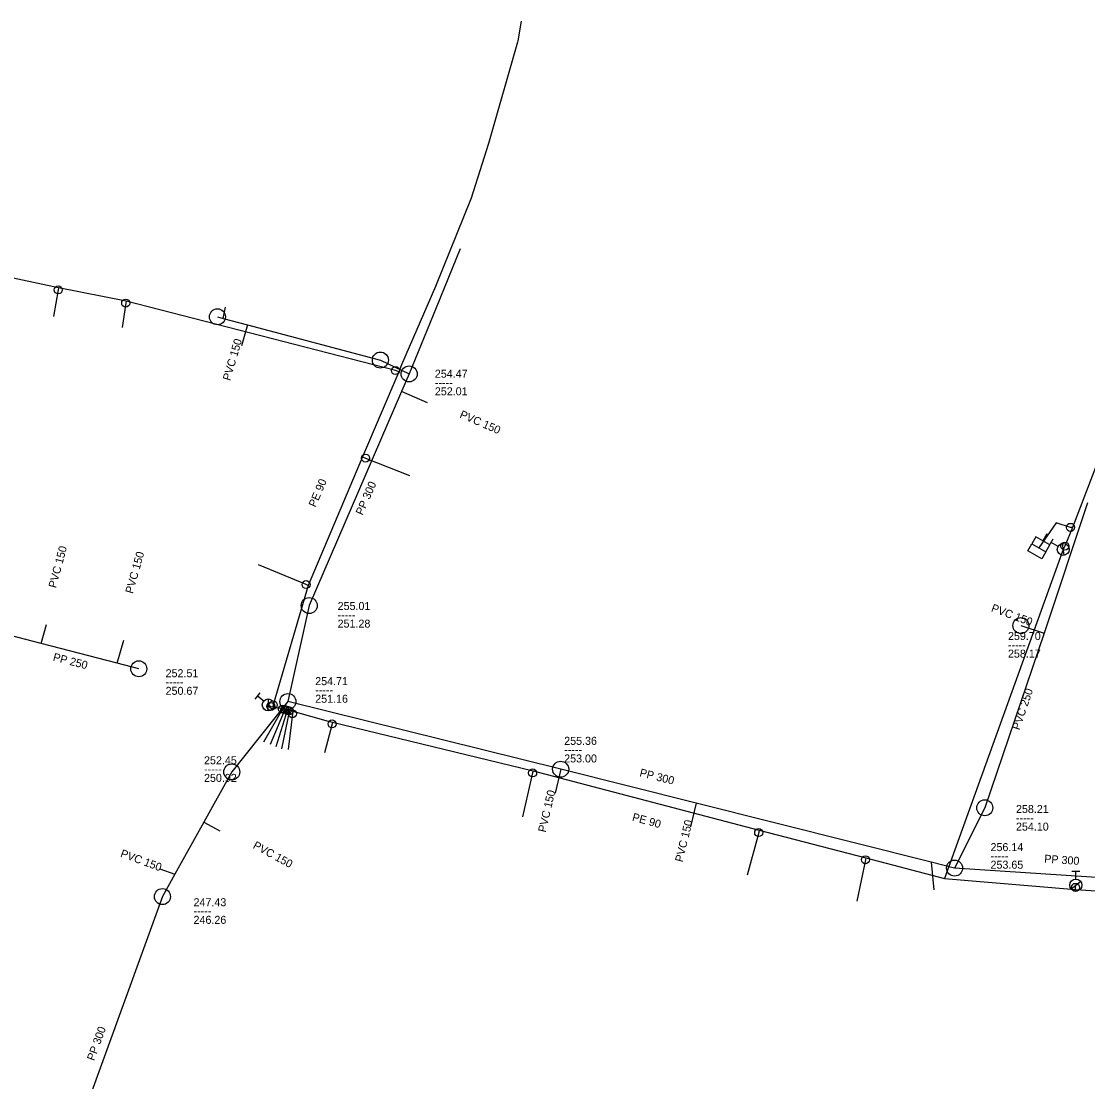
# Model space of a CAD drawing. Extents: x -771681 to -770485, y -1050143 to -1049574.
# Drawn here: x -771433.4 to -771300.2, y -1049821.1 to -1049688.6 of the extents above; entities that cross this region are included whole.
import ezdxf

# ---------------------------------------------------------------- set-up
doc = ezdxf.new("R2010")
doc.units = 0
doc.layers.add('Level 0', color=7, linetype='Continuous')

msp = doc.modelspace()

# ---------------------------------------------------------------- linework, layer by layer
at = {"layer": 'Level 0'}
for p, q in [((-771370.98, -1049688.58), (-771371.4, -1049691.01)), ((-771371.42, -1049691.2), (-771375.04, -1049703.86)), ((-771371.4, -1049691.01), (-771371.42, -1049691.2)), ((-771375.04, -1049703.86), (-771377.2, -1049710.67)), ((-771377.2, -1049710.67), (-771381.66, -1049721.72)), ((-771428.76, -1049721.9), (-771458.82, -1049715.48)), ((-771378.58, -1049717.02), (-771381.58, -1049724.37)), ((-771288.8, -1049717.07), (-771302.09, -1049751.83)), ((-771428.76, -1049721.9), (-771428.8, -1049722.15)), ((-771420.34, -1049723.55), (-771428.76, -1049721.9)), ((-771381.66, -1049721.72), (-771385.9, -1049731.53)), ((-771428.8, -1049722.15), (-771429.4, -1049725.45)), ((-771420.38, -1049723.8), (-771420.84, -1049726.85)), ((-771420.34, -1049723.55), (-771420.38, -1049723.8)), ((-771386.67, -1049732.23), (-771420.34, -1049723.55)), ((-771408.21, -1049725.7), (-771407.91, -1049724.3)), ((-771381.58, -1049724.37), (-771384.96, -1049732.65)), ((-771408.92, -1049725.51), (-771408.21, -1049725.7)), ((-771408.21, -1049725.7), (-771405.14, -1049726.51)), ((-771405.14, -1049726.51), (-771405.9, -1049729.13)), ((-771405.14, -1049726.51), (-771388.56, -1049730.91)), ((-771388.56, -1049730.91), (-771384.96, -1049732.65)), ((-771386.27, -1049732.4), (-771390.8, -1049743.02)), ((-771386.27, -1049732.4), (-771386.67, -1049732.23)), ((-771385.9, -1049731.53), (-771386.27, -1049732.4)), ((-771384.96, -1049732.65), (-771385.91, -1049734.85)), ((-771385.91, -1049734.85), (-771397.45, -1049761.6)), ((-771382.65, -1049736.26), (-771385.91, -1049734.85)), ((-771390.8, -1049743.02), (-771397.58, -1049759.09)), ((-771390.8, -1049743.02), (-771390.41, -1049743.17)), ((-771390.41, -1049743.17), (-771384.92, -1049745.35)), ((-771300.22, -1049748.75), (-771305.63, -1049765.05)), ((-771304.13, -1049751.27), (-771306.3, -1049754.37)), ((-771302.33, -1049751.82), (-771304.13, -1049751.27)), ((-771302.09, -1049751.83), (-771303.03, -1049754.17)), ((-771302.09, -1049751.83), (-771302.33, -1049751.82)), ((-771305.3, -1049752.64), (-771305.8, -1049753.5)), ((-771305, -1049754.13), (-771304.5, -1049753.26)), ((-771303.88, -1049754.2), (-771304.75, -1049753.7)), ((-771303.12, -1049755.31), (-771303.34, -1049753.83)), ((-771303.23, -1049754.57), (-771318.06, -1049795.72)), ((-771303.03, -1049754.17), (-771303.23, -1049754.57)), ((-771397.84, -1049758.98), (-771403.78, -1049756.52)), ((-771397.58, -1049759.09), (-771401.95, -1049774.02)), ((-771397.58, -1049759.09), (-771397.84, -1049758.98)), ((-771397.45, -1049761.6), (-771400.11, -1049773.6)), ((-771430.92, -1049766.32), (-771430.29, -1049763.98)), ((-771308.52, -1049764.1), (-771305.63, -1049765.05)), ((-771430.92, -1049766.32), (-771435.88, -1049765.03)), ((-771421.44, -1049768.79), (-771420.63, -1049765.9)), ((-771305.63, -1049765.05), (-771313.04, -1049786.87)), ((-771421.44, -1049768.79), (-771430.92, -1049766.32)), ((-771418.74, -1049769.5), (-771421.44, -1049768.79)), ((-771404.22, -1049773.28), (-771403.58, -1049772.51)), ((-771400.11, -1049773.6), (-771407.13, -1049782.39)), ((-771403.13, -1049773.54), (-771403.9, -1049772.9)), ((-771402.58, -1049774.77), (-771402.53, -1049773.27)), ((-771366.03, -1049782.05), (-771400.11, -1049773.6)), ((-771400.73, -1049774.45), (-771403.14, -1049778.65)), ((-771402.56, -1049774.02), (-771402.25, -1049774.2)), ((-771400.45, -1049774.51), (-771402.31, -1049778.96)), ((-771402.25, -1049774.2), (-771401.98, -1049774.24)), ((-771401.95, -1049774.02), (-771401.98, -1049774.24)), ((-771401.98, -1049774.24), (-771400.73, -1049774.45)), ((-771400.17, -1049774.6), (-771401.64, -1049779.27)), ((-771399.92, -1049774.65), (-771400.91, -1049779.48)), ((-771400.73, -1049774.45), (-771400.45, -1049774.51)), ((-771400.45, -1049774.51), (-771400.17, -1049774.6)), ((-771400.17, -1049774.6), (-771399.92, -1049774.65)), ((-771399.51, -1049774.79), (-771400.08, -1049779.58)), ((-771399.92, -1049774.65), (-771399.51, -1049774.79)), ((-771399.51, -1049774.79), (-771395.09, -1049776.03)), ((-771394.59, -1049776.39), (-771395.53, -1049780)), ((-771395.09, -1049776.03), (-771394.53, -1049776.17)), ((-771394.53, -1049776.17), (-771394.59, -1049776.39)), ((-771394.53, -1049776.17), (-771369.48, -1049782.26)), ((-771407.13, -1049782.39), (-771410.61, -1049788.65)), ((-771369.53, -1049782.5), (-771370.8, -1049787.99)), ((-771369.48, -1049782.26), (-771369.53, -1049782.5)), ((-771369.48, -1049782.26), (-771341.21, -1049789.66)), ((-771366.03, -1049782.05), (-771366.72, -1049785.02)), ((-771349.09, -1049786.3), (-771366.03, -1049782.05)), ((-771349.09, -1049786.3), (-771349.8, -1049789.25)), ((-771319.75, -1049793.66), (-771349.09, -1049786.3)), ((-771313.04, -1049786.87), (-771316.81, -1049794.4)), ((-771410.61, -1049788.65), (-771414.24, -1049795.18)), ((-771410.61, -1049788.65), (-771408.6, -1049789.75)), ((-771341.21, -1049789.66), (-771341.29, -1049789.97)), ((-771341.21, -1049789.66), (-771327.91, -1049793.13)), ((-771341.29, -1049789.97), (-771342.71, -1049795.28)), ((-771327.96, -1049793.36), (-771329.02, -1049798.55)), ((-771327.91, -1049793.13), (-771327.96, -1049793.36)), ((-771327.91, -1049793.13), (-771318.06, -1049795.72)), ((-771316.81, -1049794.4), (-771319.75, -1049793.66)), ((-771319.75, -1049793.66), (-771319.4, -1049797.11)), ((-771416.1, -1049794.49), (-771414.24, -1049795.18)), ((-771414.24, -1049795.18), (-771415.79, -1049797.97)), ((-771294.99, -1049795.85), (-771316.81, -1049794.4)), ((-771302.16, -1049794.78), (-771301.16, -1049794.78)), ((-771301.66, -1049795.78), (-771301.66, -1049794.78)), ((-771318.06, -1049795.72), (-771301.72, -1049797.07)), ((-771302.25, -1049796.99), (-771301.07, -1049796.07)), ((-771301.7, -1049796.81), (-771301.66, -1049796.53)), ((-771301.72, -1049797.07), (-771301.7, -1049796.81)), ((-771301.72, -1049797.07), (-771290.8, -1049797.76)), ((-771415.79, -1049797.97), (-771430.98, -1049839.82))]:
    msp.add_line(p, q, dxfattribs=at)
msp.add_lwpolyline([(-771305.43, -1049754.87), (-771305.93, -1049755.74), (-771307.67, -1049754.74), (-771307.17, -1049753.87)], dxfattribs=at)
msp.add_lwpolyline([(-771304.93, -1049754), (-771306.67, -1049753), (-771307.17, -1049753.87), (-771305.43, -1049754.87)], close=True, dxfattribs=at)
for centre, radius in [((-771428.8, -1049722.15), 0.5), ((-771420.38, -1049723.8), 0.5), ((-771408.92, -1049725.51), 1), ((-771388.56, -1049730.91), 1), ((-771386.67, -1049732.23), 0.5), ((-771384.96, -1049732.65), 1), ((-771390.41, -1049743.17), 0.5), ((-771302.33, -1049751.82), 0.5), ((-771303.23, -1049754.57), 0.75), ((-771303.03, -1049754.17), 0.5), ((-771397.84, -1049758.98), 0.5), ((-771397.45, -1049761.6), 1), ((-771308.52, -1049764.1), 1), ((-771418.74, -1049769.5), 1), ((-771402.56, -1049774.02), 0.75), ((-771402.25, -1049774.2), 0.5), ((-771401.95, -1049774.02), 0.5), ((-771400.11, -1049773.6), 1), ((-771400.78, -1049774.54), 0.5), ((-771400.49, -1049774.6), 0.5), ((-771400.2, -1049774.69), 0.5), ((-771399.94, -1049774.75), 0.5), ((-771399.55, -1049775.11), 0.5), ((-771394.59, -1049776.39), 0.5), ((-771407.13, -1049782.39), 1), ((-771366.03, -1049782.05), 1), ((-771369.53, -1049782.5), 0.5), ((-771313.04, -1049786.87), 1), ((-771341.29, -1049789.97), 0.5), ((-771327.96, -1049793.36), 0.5), ((-771316.81, -1049794.4), 1), ((-771301.66, -1049796.53), 0.75), ((-771301.7, -1049796.81), 0.5), ((-771415.79, -1049797.97), 1)]:
    msp.add_circle(centre, radius, dxfattribs=at)

# ---------------------------------------------------------------- texts
for s, rotation, p in [('PVC 150', 73.824, (-771407.32, -1049733.56)), ('PVC 150', 336.611, (-771378.73, -1049738.07)), ('PE 90', 67.125, (-771396.65, -1049749.38)), ('PP 300', 66.644, (-771390.77, -1049750.38)), ('PVC 150', 74.932, (-771429.09, -1049759.47)), ('PVC 150', 74.343, (-771419.49, -1049760.17)), ('PVC 150', 339.444, (-771312.32, -1049762.29)), ('PP 250', 345.421, (-771429.53, -1049768.46)), ('PVC 250', 71.243, (-771308.71, -1049777.23)), ('PP 300', 345.918, (-771356.24, -1049782.92)), ('PVC 150', 76.921, (-771367.9, -1049790)), ('PE 90', 344.329, (-771357.17, -1049788.45)), ('PVC 150', 76.468, (-771350.79, -1049793.72)), ('PVC 150', 331.31, (-771404.56, -1049791.86)), ('PVC 150', 339.647, (-771421.12, -1049792.96)), ('PP 300', 356.198, (-771305.63, -1049793.72)), ('PP 300', 70.051, (-771424.32, -1049818.55))]:
    msp.add_text(s, height=1, rotation=rotation, dxfattribs=at).set_placement(p)
for s, p in [('254.47', (-771381.75, -1049733.12)), ('-----', (-771381.75, -1049734.22)), ('252.01', (-771381.75, -1049735.32)), ('255.01', (-771393.9, -1049762.15)), ('-----', (-771393.9, -1049763.25)), ('251.28', (-771393.9, -1049764.35)), ('259.70', (-771310.14, -1049765.9)), ('-----', (-771310.14, -1049767)), ('258.17', (-771310.14, -1049768.1)), ('252.51', (-771415.39, -1049770.55)), ('-----', (-771415.39, -1049771.65)), ('254.71', (-771396.7, -1049771.54)), ('250.67', (-771415.39, -1049772.75)), ('-----', (-771396.7, -1049772.64)), ('251.16', (-771396.7, -1049773.74)), ('255.36', (-771365.59, -1049779)), ('252.45', (-771410.59, -1049781.43)), ('-----', (-771365.59, -1049780.1)), ('253.00', (-771365.59, -1049781.2)), ('-----', (-771410.59, -1049782.53)), ('250.92', (-771410.59, -1049783.63)), ('258.21', (-771309.14, -1049787.52)), ('-----', (-771309.14, -1049788.62)), ('254.10', (-771309.14, -1049789.72)), ('256.14', (-771312.32, -1049792.28)), ('-----', (-771312.32, -1049793.38)), ('253.65', (-771312.32, -1049794.48)), ('247.43', (-771411.9, -1049799.17)), ('-----', (-771411.9, -1049800.27)), ('246.26', (-771411.9, -1049801.37))]:
    msp.add_text(s, height=1, dxfattribs=at).set_placement(p)

doc.saveas('drawing.dxf')
